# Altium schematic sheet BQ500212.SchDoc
size A2
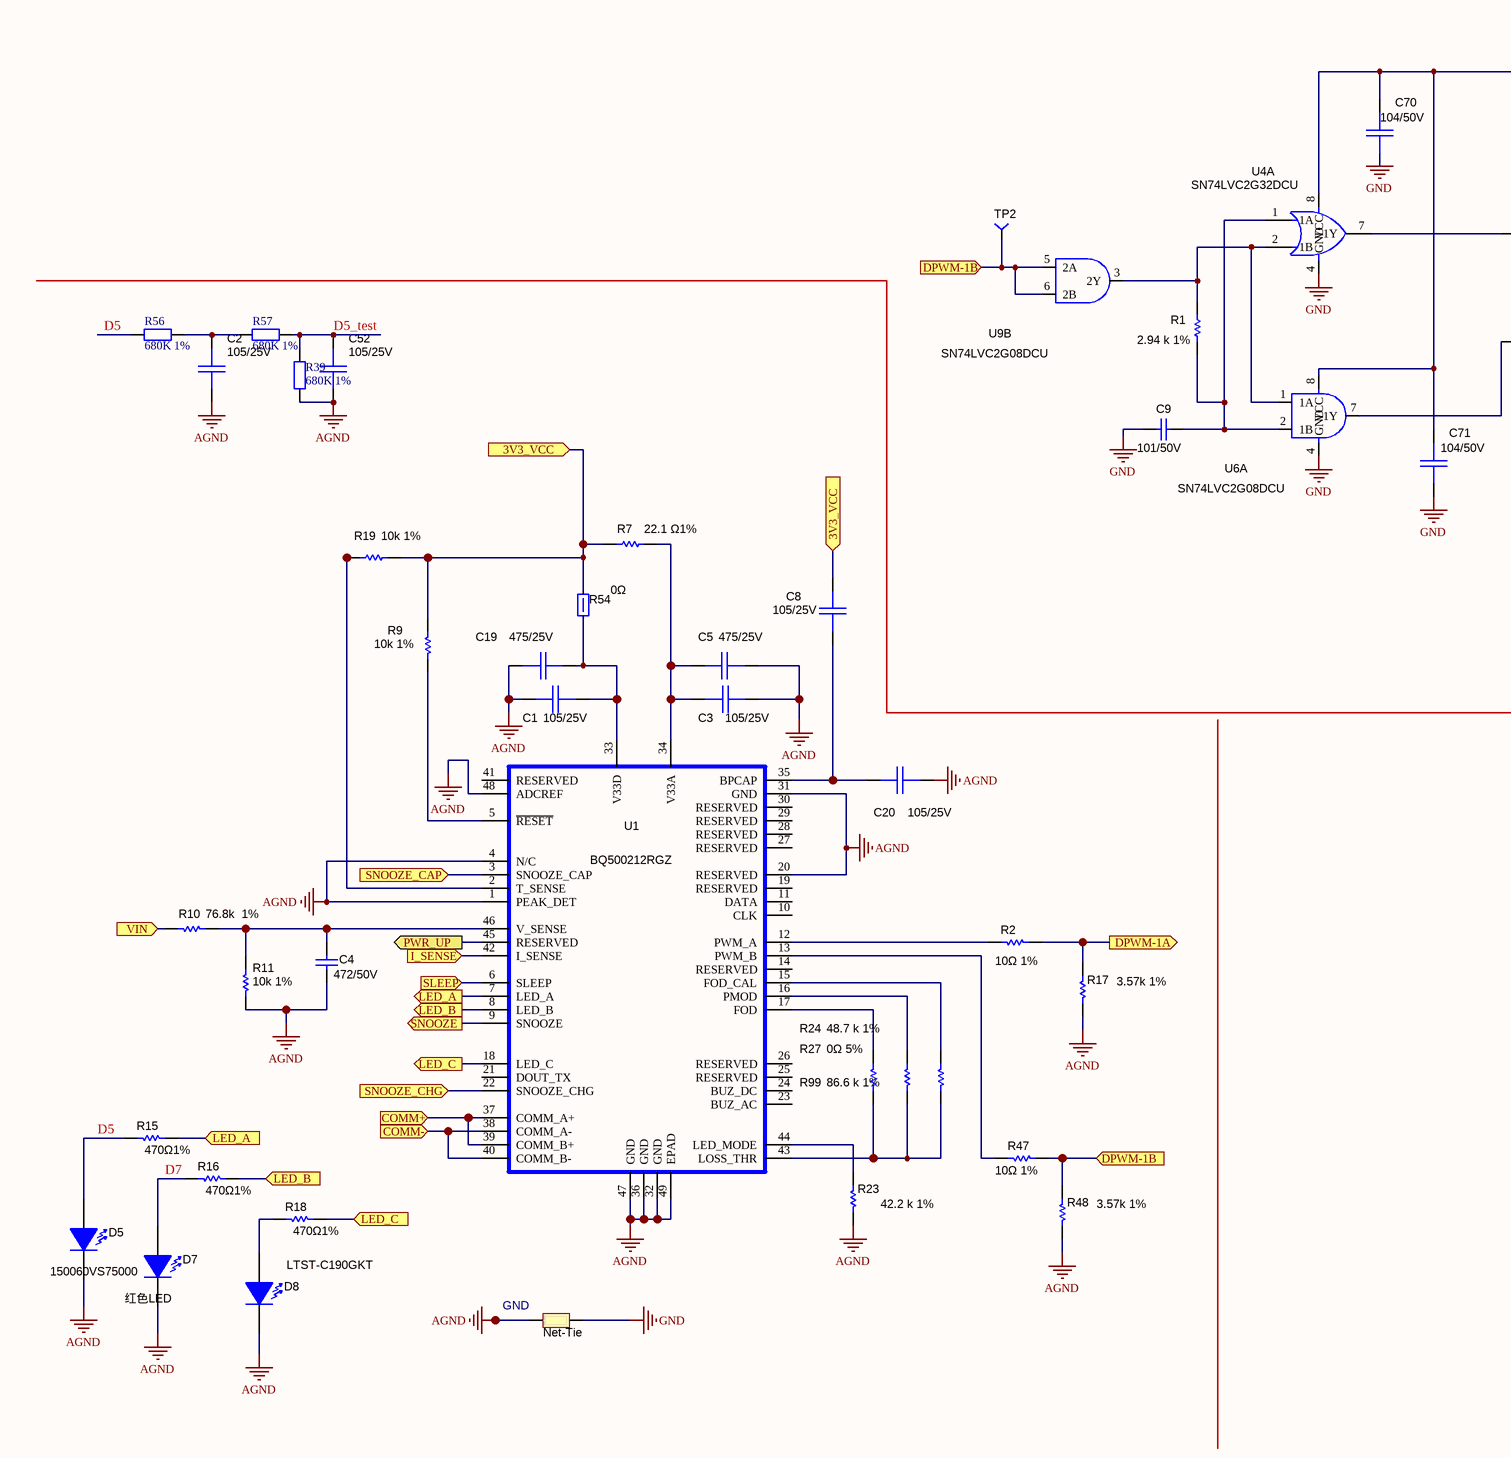
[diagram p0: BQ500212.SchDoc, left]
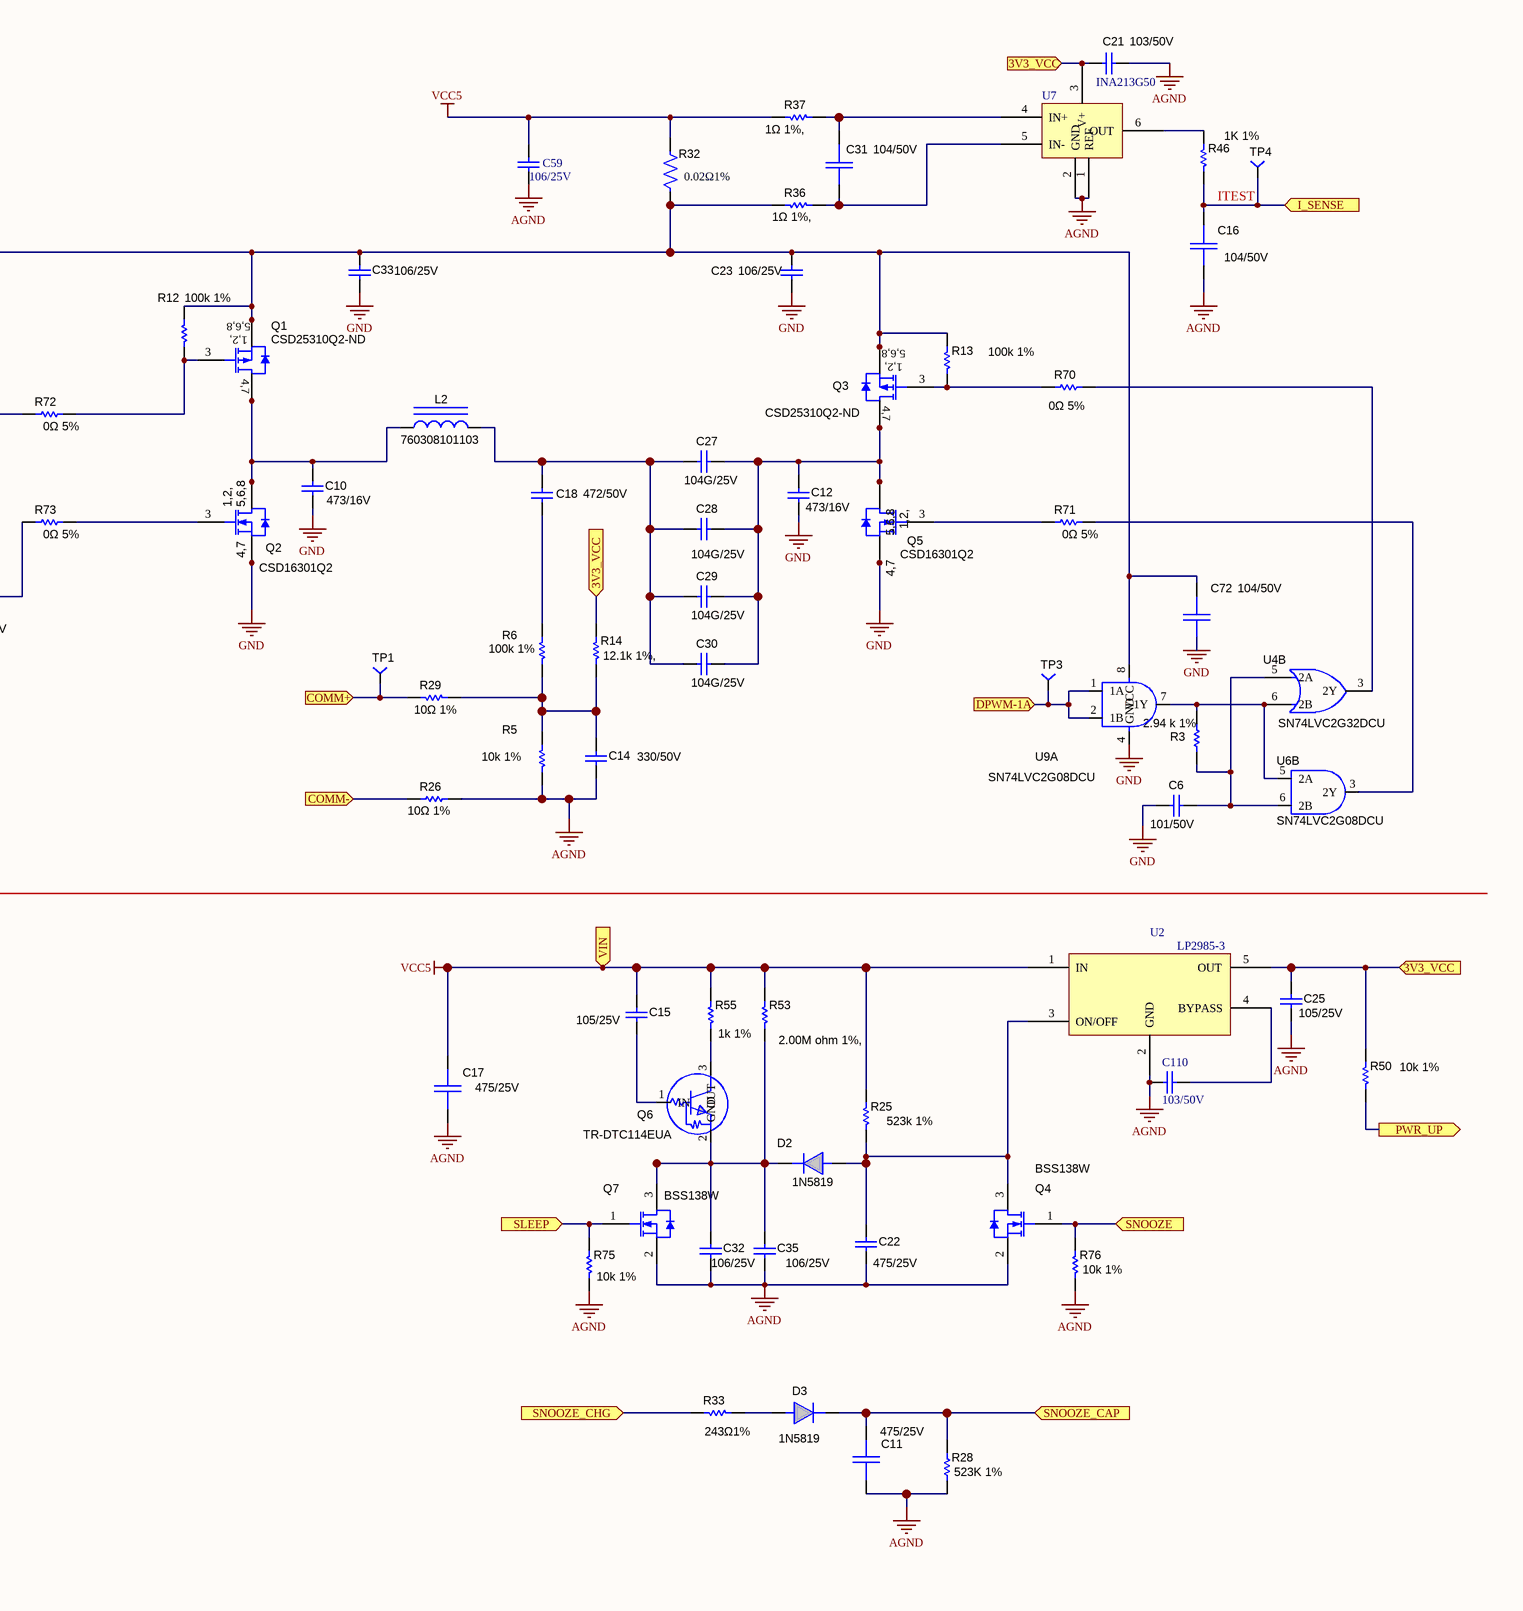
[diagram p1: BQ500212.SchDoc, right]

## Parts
1A1  Net-Tie  [Net-Tie_10milWide_30milLong]  (net tie, no BOM)
C1  105/25V  [C0805]
C2  105/25V  [C0805]
C3  105/25V  [C0805]
C4  472/50V  [C0402]
C5  475/25V  [C0805]
C6  101/50V  [C0603]
C8  105/25V  [C0805]
C9  101/50V  [C0603]
C10  473/16V  [0603L]
C11  475/25V  [C0805]
C12  473/16V  [0603L]
C14  330/50V  [C0402]
C15  105/25V  [C0805]
C16  104/50V  [C0402]
C17  475/25V  [C0805]
C18  472/50V  [C0402]
C19  475/25V  [C0805]
C20  105/25V  [C0805]
C21  103/50V  [C0402]
C22  475/25V  [C0805]
C23  106/25V  [C1206]
C25  105/25V  [C0805]
C27  104G/25V  [1206L]
C28  104G/25V  [1206L]
C29  104G/25V  [1206L]
C30  104G/25V  [1206L]
C31  104/50V  [C0402]
C32  106/25V  [C0805]
C33  106/25V  [C1206]
C35  106/25V  [C0805]
C52  105/25V  [C0805]
C59  106/25V  [C1206]
C70  104/50V  [C0402]
C71  104/50V  [C0402]
C72  104/50V  [C0402]
C110  103/50V  [C0603]
D2  1N5819  [SOD-323]
D3  1N5819  [SOD-323]
D5  150060VS75000  [c0805]
D7  红色LED  [c0805]
D8  LTST-C190GKT  [c0805]
L2  760308101103  [HDR1X2]
Q1  CSD25310Q2-ND  [TRANS_NexFET_Q2]
Q2  CSD16301Q2  [TRANS_NexFET_Q2]
Q3  CSD25310Q2-ND  [TRANS_NexFET_Q2]
Q4  BSS138W  [SOT-323]
Q5  CSD16301Q2  [TRANS_NexFET_Q2]
Q6  TR-DTC114EUA  [SOT-323]
Q7  BSS138W  [SOT-323]
R1  2.94 k 1%  [RC0402]
R2  10Ω 1%  [RC0402]
R3  2.94 k 1%  [RC0402]
R5  10k 1%  [RC0402]
R6  100k 1%  [RC0402]
R7  22.1 Ω1%  [RC0402]
R9  10k 1%  [RC0402]
R10  76.8k  1%  [RC0402]
R11  10k 1%  [RC0402]
R12  100k 1%  [RC0402]
R13  100k 1%  [RC0402]
R14  12.1k 1%,  [RC0402]
R15  470Ω1%  [RC0402]
R16  470Ω1%  [RC0402]
R17  3.57k 1%  [RC0402]
R18  470Ω1%  [RC0402]
R19  10k 1%  [RC0402]
R23  42.2 k 1%  [RC0402]
R24  48.7 k 1%  [RC0402]
R25  523k 1%  [RC0402]
R26  10Ω 1%  [RC0402]
R27  0Ω 5%  [RC0402]
R28  523K 1%  [RC0402]
R29  10Ω 1%  [RC0402]
R32  0.02Ω1%  [R0603]
R33  243Ω1%  [RC0402]
R36  1Ω 1%,  [RC0402]
R37  1Ω 1%,  [RC0402]
R39  680K 1%  [RC0402]
R46  1K 1%  [RC0402]
R47  10Ω 1%  [RC0402]
R48  3.57k 1%  [RC0402]
R50  10k 1%  [RC0402]
R53  2.00M ohm 1%,  [RC0402]
R54  0Ω  [R0603]
R55  1k 1%  [RC0402]
R56  680K 1%  [RC0402]
R57  680K 1%  [RC0402]
R70  0Ω 5%  [RC0402]
R71  0Ω 5%  [RC0402]
R72  0Ω 5%  [RC0402]
R73  0Ω 5%  [RC0402]
R75  10k 1%  [RC0402]
R76  10k 1%  [RC0402]
R99  86.6 k 1%  [RC0402]
TP1  TP-025-SMT  [TP_25MIL-SMT]  (value not drawn)
TP2  TP-025-SMT  [TP_25MIL-SMT]  (value not drawn)
TP3  TP-025-SMT  [TP_25MIL-SMT]  (value not drawn)
TP4  TP-025-SMT  [TP_25MIL-SMT]  (value not drawn)
U1  BQ500212RGZ  [QFN48[RGZ]]
U2  LP2985-3  [SOT23-5]
U4  SN74LVC2G32DCU  [VSSOP8]  (parts A,B of 2)
U6  SN74LVC2G08DCU  [VSSOP8]  (parts A,B of 2)
U7  INA213G50  [DCK6]
U9  SN74LVC2G08DCU  [VSSOP8]  (parts A,B of 2)

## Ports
3V3_VCC, COMM+, COMM-, DPWM-1A, DPWM-1B, I_SENSE, LED_A, LED_B, LED_C, PWR_UP, SLEEP, SNOOZE, SNOOZE_CAP, SNOOZE_CHG, VIN

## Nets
AGND: 1A1.2 C1.1 C2.1 C3.1 C4.2 C5.2 C11.2 C14.1 C16.1 C17.2 C19.2 C20.2 C21.1 C22.2 C25.2 C32.2 C35.2 C52.1 C59.2 C110.1 D5.1(K) D7.1(K) D8.2(K) Q4.2(S) Q7.2(S) R5.1 R11.1 R17.1 R23.1 R26.2 R28.1 R39.2 R48.1 R75.1 R76.1 U1.1(PEAK_DET) U1.4(N/C) U1.20(RESERVED) U1.31(GND) U1.32(GND) U1.36(GND) U1.47(GND) U1.48(ADCREF) U1.49(EPAD) U2.2(GND) U7.1(REF) U7.2(GND)
GND: 1A1.1 C6.2 C9.2 C10.2 C12.2 C23.2 C33.2 C70.1 C71.1 C72.1 Q2.4(S) Q2.7(S) Q5.4(S) Q5.7(S) U4.4(GND) U6.4(GND) U9.4(GND)
VCC5: C15.1 C17.1 C59.1 R10.2 R25.2 R32.2 R37.1 R53.2 R55.2 U2.1(IN) ; port VIN
3V3_VCC: C8.1 C21.2 C25.1 R7.2 R9.2 R14.2 R19.1 R50.2 R54.2 U2.5(OUT) U7.3(V+) ; port 3V3_VCC
COMM+: R29.1 TP1.1 U1.37(COMM_A+) U1.39(COMM_B+) ; port COMM+
COMM-: R26.1 U1.38(COMM_A-) U1.40(COMM_B-) ; port COMM-
D5: D5.2(A) R15.2 R56.2
D5_test: C52.2 R39.1 R57.1
D7: D7.2(A) R16.2
DPWM-1A: R2.2 R17.2 TP3.1 U9.1(1A) U9.2(1B) ; port DPWM-1A
DPWM-1B: R47.2 R48.2 TP2.1 U9.5(2A) U9.6(2B) ; port DPWM-1B
ITEST: C16.2 R46.1 TP4.1 U1.42(I_SENSE) ; port I_SENSE
LED_A: R15.1 U1.7(LED_A) ; port LED_A
LED_B: R16.1 U1.8(LED_B) ; port LED_B
LED_C: R18.1 U1.18(LED_C) ; port LED_C
PWR_UP: R50.1 U1.45(RESERVED) ; port PWR_UP
SLEEP: Q7.1(G) R75.2 U1.6(SLEEP) ; port SLEEP
SNOOZE: Q4.1(G) R76.2 U1.9(SNOOZE) ; port SNOOZE
SNOOZE_CAP: C11.1 D3.1 R28.2 U1.3(SNOOZE_CAP) ; port SNOOZE_CAP
SNOOZE_CHG: R33.2 U1.22(SNOOZE_CHG) ; port SNOOZE_CHG
NetC1_2: C1.2 C19.1 R54.1 U1.33(V33D)
NetC2_2: C2.2 R56.1 R57.2
NetC3_2: C3.2 C5.1 R7.1 U1.34(V33A)
NetC4_1: C4.1 R10.1 R11.2 U1.46(V_SENSE)
NetC6_1: C6.1 R3.1 U4.5(2A) U6.6(2B)
NetC8_2: C8.2 C20.1 U1.35(BPCAP)
NetC9_1: C9.1 R1.1 U4.1(1A) U6.2(1B)
NetC10_1: C10.1 L2.1 Q1.4(D) Q1.7(D) Q2.1(D) Q2.2(D) Q2.5(D) Q2.6(D) Q2.8(D)
NetC12_1: C12.1 C27.1 C28.1 C29.1 C30.1 Q3.4(D) Q3.7(D) Q5.1(D) Q5.2(D) Q5.5(D) Q5.6(D) Q5.8(D)
NetC14_2: C14.2 R5.2 R6.1 R14.1 R29.2
NetC15_2: C15.2 Q6.1(IN)
NetC18_1: C18.1 R6.2
NetC18_2: C18.2 C27.2 C28.2 C29.2 C30.2 L2.2
NetC22_1: C22.1 D2.2 Q4.3(D) R25.1 U2.3(ON/OFF)
NetC23_1: C23.1 C33.1 C70.2 C71.2 C72.2 Q1.1(S) Q1.2(S) Q1.5(S) Q1.6(S) Q1.8(S) Q3.1(S) Q3.2(S) Q3.5(S) Q3.6(S) Q3.8(S) R12.2 R13.2 R32.1 R36.1 U4.8(VCC) U6.8(VCC) U9.8(VCC)
NetC31_1: C31.1 R36.2 U7.5(IN-)
NetC31_2: C31.2 R37.2 U7.4(IN+)
NetC32_1: C32.1 C35.1 D2.1 Q6.2(GND) Q7.3(D) R53.1
NetC110_2: C110.2 U2.4(BYPASS)
NetD3_2: D3.2 R33.1
NetD8_1: D8.1(A) R18.2
NetQ1_3: Q1.3(G) R12.1 R72.2
NetQ2_3: Q2.3(G) R73.2
NetQ3_3: Q3.3(G) R13.1 R70.1
NetQ5_3: Q5.3(G) R71.1
NetQ6_3: Q6.3(OUT) R55.1
NetR1_2: R1.2 U4.2(1B) U6.1(1A) U9.3(2Y)
NetR2_1: R2.1 U1.12(PWM_A)
NetR3_2: R3.2 U4.6(2B) U6.5(2A) U9.7(1Y)
NetR9_1: R9.1 U1.5(~{RESET})
NetR19_2: R19.2 U1.2(T_SENSE)
NetR23_2: R23.2 U1.44(LED_MODE)
NetR24_1: R24.1 R27.1 R99.1 U1.43(LOSS_THR)
NetR24_2: R24.2 U1.17(FOD)
NetR27_2: R27.2 U1.16(PMOD)
NetR46_2: R46.2 U7.6(OUT)
NetR47_1: R47.1 U1.13(PWM_B)
NetR70_2: R70.2 U4.3(2Y)
NetR71_2: R71.2 U6.3(2Y)
NetR72_1: R72.1 U4.7(1Y)
NetR73_1: R73.1 U6.7(1Y)
NetR99_2: R99.2 U1.15(FOD_CAL)

Not connected (* = marked no-connect by the designer): U1 10(CLK) 11(DATA) 14(RESERVED) 19(RESERVED) 21(DOUT_TX) 23(BUZ_AC) 24(BUZ_DC) 25(RESERVED) 26(RESERVED) 27(RESERVED) 28(RESERVED) 29(RESERVED) 30(RESERVED) 41(RESERVED)

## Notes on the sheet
- (near 1A1) GND

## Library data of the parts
1A1 = Net-Tie: Single point connection between nets.; SymbolCreator: codlsc
C1-C3 C8 C20 C52 = C0603: Capacitor; Manufacturer: STD; Description: Capacitor, Ceramic, 16V, X7R, 20%; Value: 1.0uF; Area: 5650
C4 C18 = C1005X7R1H472K: Capacitor; Manufacturer: TDK; Polarized: N; Value: 4700pF; U/M: EA; Cap_F: 0.0000000047; Tolerance_%: 10; ESR_Ohm: 0.0826; Value1: 0.0826 ohm; VDC_V: 50; Value2: 50V; TempCo: X7R; TaMin_C: -55; TaMax_C: 125; Cap_Case: 0402
C5 C11 C19 = C0603: Capacitor; Manufacturer: STD; Description: Capacitor, Ceramic, 10V, X5R, 20%; Value: 4.7uF; Area: 5650
C6 C9 = GRM1555C1H101JA01D: Capacitor; Manufacturer: MuRata; Polarized: N; Value: 100pF; U/M: EA; Cap_F: 0.0000000001; Tolerance_%: 5; Value1: Unknown; VDC_V: 50; Value2: 50V; TempCo: C0G/NP0; TaMin_C: -55; TaMax_C: 125; Cap_Case: 0402
C10 C12 = GRM188R71C473KA01D: Capacitor; Manufacturer: MuRata; Polarized: N; Value: 0.047uF; ValueDisplayed: 0.047µF; U/M: EA; Cap_F: 0.000000047; Tolerance_%: 10; Value1: Unknown; VDC_V: 16; Value2: 16V; TempCo: X7R; TaMin_C: -55; TaMax_C: 125; Cap_Case: 0603
C14 = GRM1555C1H330JA01D: Capacitor; Manufacturer: MuRata; Polarized: N; Value: 33pF; U/M: EA; Cap_F: 0.000000000033; Tolerance_%: 5; Value1: Unknown; VDC_V: 50; Value2: 50V; TempCo: C0G/NP0; TaMin_C: -55; TaMax_C: 125; Cap_Case: 0402
C15 C25 = GRM155R61A105KE15D: Capacitor; Manufacturer: MuRata; Polarized: N; Value: 1uF; ValueDisplayed: 1µF; U/M: EA; Cap_F: 0.000001; Tolerance_%: 10; Value1: Unknown; Value2: 10V; TempCo: X5R; TaMin_C: -55; TaMax_C: 85; Cap_Case: 0402
C16 C31 C70-C72 = C0402: Capacitor; Manufacturer: STD; Area: 2800; Value: 0.1uF
C17 = C0603: Capacitor; Manufacturer: STD; Value: 4.7uF; Area: 5650
C21 = GRM155R71H103KA88D: Capacitor; Manufacturer: MuRata; Polarized: N; Value: 0.01uF; ValueDisplayed: 0.01µF; U/M: EA; Cap_F: 0.00000001; Tolerance_%: 10; Value1: Unknown; VDC_V: 50; Value2: 50V; TempCo: X7R; TaMin_C: -55; TaMax_C: 125; Cap_Case: 0402
C22 = GRM155R61A475M: Capacitor; Manufacturer: MuRata; Polarized: N; Value: 4.7uF; ValueDisplayed: 4.7µF; U/M: EA; Cap_F: 0.0000047; Tolerance_%: 20; Value1: Unknown; VDC_V: 10; Value2: 10V; TempCo: X5R; TaMin_C: -55; TaMax_C: 85; Cap_Case: 0402
C23 C33 = EMK107BBJ106MA-T: Capacitor; Manufacturer: Taiyo Yuden; Polarized: N; Value: 10uF; ValueDisplayed: 10µF; U/M: EA; Cap_F: 0.00001; Tolerance_%: 20; Value1: Unknown; VDC_V: 16; Value2: 16V; TempCo: X5R; TaMin_C: -55; TaMax_C: 85; Cap_Case: 0603
C27-C30 = C3216C0G1E104J: Capacitor; Manufacturer: TDK; Polarized: N; Value: 0.1uF; ValueDisplayed: 0.1µF; U/M: EA; Cap_F: 0.0000001; Tolerance_%: 5; Value1: Unknown; VDC_V: 25; Value2: 25V; TempCo: C0G/NP0; TaMin_C: -55; TaMax_C: 125; Cap_Case: 1206
C32 C35 = C1608X5R0J226M080AC: Capacitor; Manufacturer: TDK; Polarized: N; Value: 22uF; ValueDisplayed: 22µF; U/M: EA; Cap_F: 0.000022; Tolerance_%: 20; Value1: Unknown; VDC_V: 6.3; Value2: 6.3V; TempCo: X5R; TaMin_C: -55; TaMax_C: 85; Cap_Case: 0603
C59 = Cap: Capacitor; Value: 104pF/50V
C110 = Cap: Capacitor; Value: 104
D2 D3 = D-BAV_SOD323: Diode, Small Signal, 200-mA, 30-V; Manufacturer: Fairchild; Value: BAT54HT1G; Area: 16600
D5 = 150060VS75000: LED, Green, SMD; Manufacturer: Wurth Elektronik eiSos; Type: AlInGaP; Vf_V: 2; Value2: 2V; Io_A: 0.02; Value1: W; U/M: EA
D7 = 150060SS75000: LED, Super Red, SMD; Manufacturer: Wurth Elektronik eiSos; Type: AlInGaP; Vf_V: 1.9; Value2: 1.9V; Io_A: 0.02; Value1: W; U/M: EA
D8 = LTST-C190GKT: LED, Green, SMD; Manufacturer: Lite-On; Value: NoPop; Vf_V: 2.1; Value2: 2.1V; Io_A: 0.02; Power_TotalModule: 0.1; Value1: 0.1W; U/M: EA
L2 = 760308101103: Coil TX Wireless Power, 30mm X 2mm; Manufacturer: Wurth Elektronik eiSos; CompType: Inductor; Value: 6.5uH; Ind_H: 6.5E-6; ValueDisplayed: 6.5µH; Imax_A: 3; Irms: 3A @ 40C rise; Isat: 8A @ % inductance drop; DCR_ohm: 0.15; Value1: 0.15 ohm; Value2: 3A
Q1 Q3 = CSD25310Q2: MOSFET, P-CH, -20 V, -20 A, SON 2x2mm; Manufacturer: Texas Instruments; Alternate Manufacturer: None; SymbolCreator: a0411947; U/M: EA; ChType: P; Value: -20V; Value1: 0.0239 ohm; Rdson45_ohm: 0.0239; Value2: 3.6 nC; QgTyp_nC: 3.6; Vgs_V: 8
Q2 Q5 = CSD16301Q2: MOSFET, N-CH, 25V, 5A, SON 2x2mm; Manufacturer: Texas Instruments; Alternate Manufacturer: None; U/M: EA; ChType: N; VdsMax_V: 25; Value1: 0.023 ohm; Rdson45_Ohm: 0.023; Value2: 2 nC; QgTyp_nC: 2; Vgs_V: 10; IdsMax_A: 5
Q4 Q7 = BSS138W-7-F: MOSFET, N-CH, 50V, 0.2A, SOT-323; Manufacturer: Diodes Inc.; Alternate Manufacturer: None; U/M: EA; ChType: N; VdsMax_V: 50; Value1: 3.5 ohm; Rdson45_Ohm: 3.5; Value2: ? nC; Vgs_V: 1.5; IdsMax_A: 0.2
Q6 = TR-DTC114EUA: Transistor, Digital NPN, 50 V, 100 mA; Manufacturer: Rohm; Area: 23010
R1 R3 = CRCW04022K94FKED: Resistor; Manufacturer: Vishay-Dale; Value: 2.94k; U/M: EA; Res_ohm: 2940; Value_Code: 2k94; Tolerance_%: 1; Power_W: 0.063; Value2: 0.063W; VDC_V: 50; TempCo: 100 ppm/C; EIA_Code: E96
R2 R26 R29 R47 = CRCW040210R0FKED: Resistor; Manufacturer: Vishay-Dale; Value: 10.0; Res_ohm: 10; Value_Code: 10R0; Tolerance_%: 1; Power_W: 0.063; Value2: 0.063W; VDC_V: 50; TempCo: 100 ppm/C; EIA_Code: E96; U/M: EA
R5 R9 R11 R19 R50 R75 R76 = CRCW040210K0FKED: Resistor; Manufacturer: Vishay-Dale; Value: 10.0k; Res_ohm: 10000; Value_Code: 10k0; Tolerance_%: 1; Power_W: 0.063; Value2: 0.063W; VDC_V: 50; TempCo: 100 ppm/C; EIA_Code: E96; U/M: EA
R6 R12 R13 = CRCW0402100KFKED: Resistor; Manufacturer: Vishay-Dale; Res_ohm: 100000; Tolerance_%: 1; Power_W: 0.063; Value2: 0.063W; VDC_V: 50; TempCo: 100 ppm/C; EIA_Code: E96; U/M: EA
R7 = CRCW040222R1FKED: Resistor; Manufacturer: Vishay-Dale; Value: 22.1; Value_Code: 22R1; Tolerance_%: 1; Value1: 1%; Power_W: 0.063; Value2: 0.063W; VDC_V: 50; TempCo: 100 ppm/C; EIA_Code: E96; U/M: EA
R10 = CRCW040276K8FKED: Resistor; Manufacturer: Vishay-Dale; Res_ohm: 76800; Value_Code: 76k8; Tolerance_%: 1; Power_W: 0.063; Value2: 0.063W; VDC_V: 50; TempCo: 100 ppm/C; EIA_Code: E96; U/M: EA
R14 = CRCW040212K1FKED: Resistor; Manufacturer: Vishay-Dale; Res_ohm: 12100; Value_Code: 12k1; Tolerance_%: 1; Power_W: 0.063; Value2: 0.063W; VDC_V: 50; TempCo: 100 ppm/C; EIA_Code: E96; U/M: EA
R15 R16 = CRCW0402475RFKED: Resistor; Manufacturer: Vishay-Dale; Value: 475; Value_Code: 475R; Tolerance_%: 1; Value1: 1%; Power_W: 0.063; Value2: 0.063W; VDC_V: 50; TempCo: 100 ppm/C; EIA_Code: E96; U/M: EA; ValueDisplayed: 470
R17 R48 = CRCW04023K57FKED: Resistor; Manufacturer: Vishay-Dale; Res_ohm: 3570; Value_Code: 3k57; Tolerance_%: 1; Power_W: 0.063; Value2: 0.063W; VDC_V: 50; TempCo: 100 ppm/C; EIA_Code: E96; U/M: EA
R18 = CRCW0402475RFKED: Resistor; Manufacturer: Vishay-Dale; Value: NoPop; Res_ohm: 475; Value_Code: 475R; Tolerance_%: 1; Value1: 1%; Power_W: 0.063; Value2: 0.063W; VDC_V: 50; TempCo: 100 ppm/C; EIA_Code: E96; U/M: EA
R23 = CRCW040242K2FKED: Resistor; Manufacturer: Vishay-Dale; Value: 42.2k; Res_ohm: 42200; Value_Code: 42k2; Tolerance_%: 1; Power_W: 0.063; Value2: 0.063W; VDC_V: 50; TempCo: 100 ppm/C; EIA_Code: E96; U/M: EA
R24 = CRCW040248K7FKED: Resistor; Manufacturer: Vishay-Dale; Value: NoPop; Res_ohm: 48700; Value_Code: 48k7; Tolerance_%: 1; Power_W: 0.063; Value2: 0.063W; VDC_V: 50; TempCo: 100 ppm/C; EIA_Code: E96; U/M: EA; ValueDisplayed: 48.7k
R25 R28 = CRCW0402523KFKED: Resistor; Manufacturer: Vishay-Dale; Res_ohm: 523000; Tolerance_%: 1; Power_W: 0.063; Value2: 0.063W; VDC_V: 50; TempCo: 100 ppm/C; EIA_Code: E96; U/M: EA
R27 = CRCW04020000Z0ED: Resistor; Manufacturer: Vishay-Dale; Value: NoPop; Res_ohm: 0; Value_Code: 0000; Tolerance_%: 5; Power_W: 0.063; Value2: 0.063W; VDC_V: 50; TempCo: 200 ppm/C; EIA_Code: E24; U/M: EA
R32 = R603: Resistor; Manufacturer: Vishay Dale; PartNumber: WSL0603R0200FEA; Area: 9,100; Value: .020 Ohm
R33 = CRCW0402243RFKED: Resistor; Manufacturer: Vishay-Dale; Value: 243; Value_Code: 243R; Tolerance_%: 1; Value1: 1%; Power_W: 0.063; Value2: 0.063W; VDC_V: 50; TempCo: 100 ppm/C; EIA_Code: E96; U/M: EA
R36 R37 = CRCW04021R00FKED: Resistor; Manufacturer: Vishay-Dale; Value: 1.00; Res_ohm: 1; Value_Code: 1R00; Power_W: 0.063; Value2: 0.063W; VDC_V: 50; TempCo: 100 ppm/C; EIA_Code: E96; U/M: EA
R39 R56 R57 = Res: Resistor; Value: 1K
R46 R55 = CRCW04021K00FKED: Resistor; Manufacturer: Vishay-Dale; Value: 1.00k; Res_ohm: 1000; Value_Code: 1k00; Tolerance_%: 1; Power_W: 0.063; Value2: 0.063W; VDC_V: 50; TempCo: 100 ppm/C; EIA_Code: E96; U/M: EA
R53 = CRCW04022M00FKED: Resistor; Manufacturer: Vishay-Dale; Value: 2.00Meg; Res_ohm: 2000000; Value_Code: 2M00; Tolerance_%: 1; Power_W: 0.063; Value2: 0.063W; VDC_V: 50; TempCo: 100 ppm/C; EIA_Code: E96; U/M: EA
R54 = BLM15HG102SN1D: 0.25A Ferrite Bead, 1000 ohm @ 100MHz, SMD; Manufacturer: MuRata; Imax_A: 0.25; Irms: 0.25A @ C rise; Isat: 0.25A @ % inductance drop; DCR_ohm: 1.1; Value1: 1.1 ohm; ZTyp@100MHz_Ohm: 1000; U/M: EA
R70-R73 = CRCW04020000Z0ED: Resistor; Manufacturer: Vishay-Dale; Value: 0; Value_Code: 0000; Tolerance_%: 5; Power_W: 0.063; Value2: 0.063W; VDC_V: 50; TempCo: 200 ppm/C; EIA_Code: E24; U/M: EA
R99 = CRCW040286K6FKED: Resistor; Manufacturer: Vishay-Dale; Value: NoPop; Res_ohm: 86600; Value_Code: 86k6; Tolerance_%: 1; Power_W: 0.063; Value2: 0.063W; VDC_V: 50; TempCo: 100 ppm/C; EIA_Code: E96; U/M: EA; ValueDisplayed: 86.6k
TP1-TP4 = TP-025-SMT: Test Point, O.025"; Manufacturer: STD; Value: STD
U1 = BQ500210RGZ: IC, Qi Compliant Wireless Power Transmitter Manager; PartNumber: BQ500212ARGZ; Manufacturer: TI; Alternate Manufacturer: None; Area: 115600; Value: BQ500212A
U2 = LP2985
U4 = SN74LVC2G32DCU: IC, Dual 2-Input Positive-OR Gates; PartNumber: SN74LVC2G32DCUx; Manufacturer: TI; Alternate Manufacturer: None; Area: 21.390; Value: SN74LVC2G32DCUx
U6 U9 = SN74LVC2G08DCU: Dual 2-Input Positive-And Gate; Manufacturer: TI; Alternate Manufacturer: None; Area: 36735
